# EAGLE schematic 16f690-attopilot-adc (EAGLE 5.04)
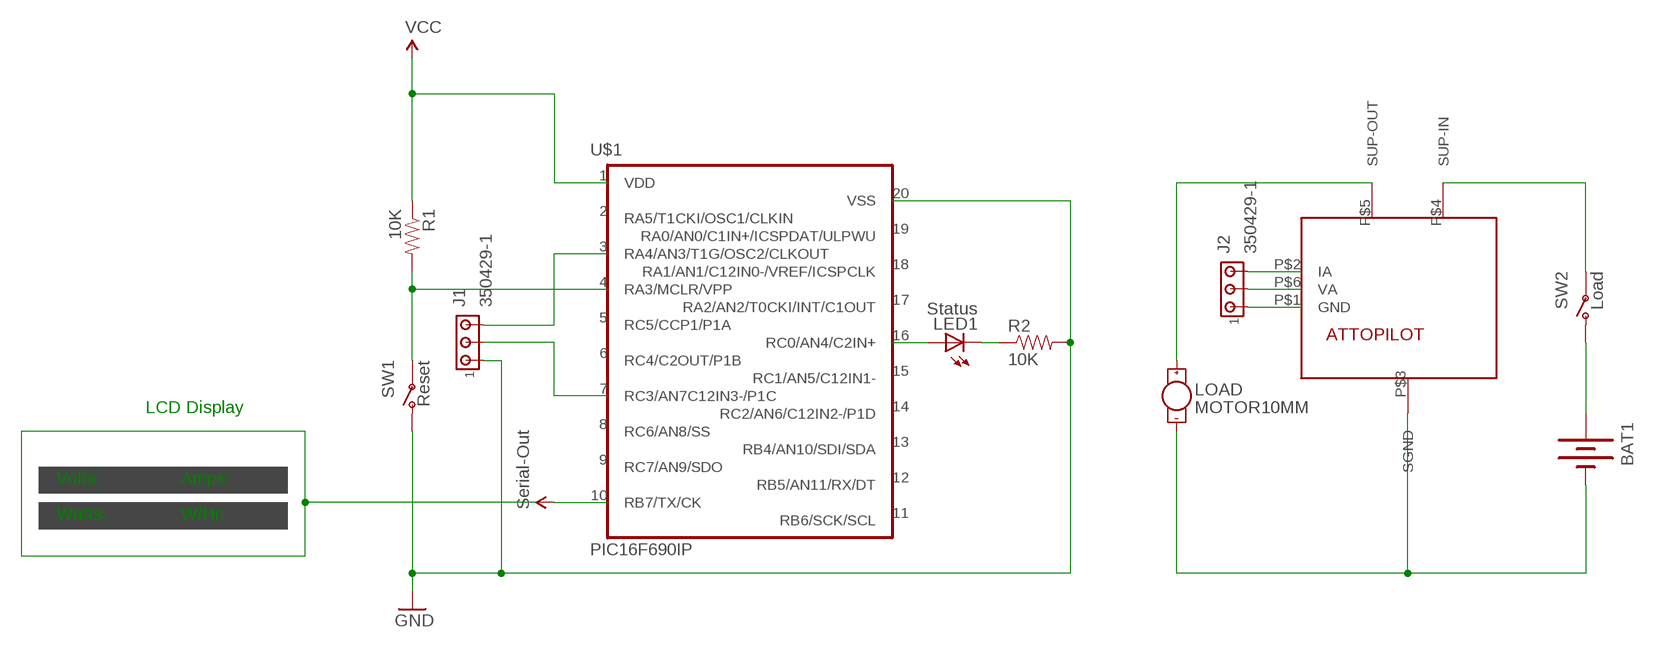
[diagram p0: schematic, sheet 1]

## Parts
ATTOPILOT  ATTOPILOT  [ATTOPILOT]
BAT1  BATTERYAA  [BATTERY-AA]
J1  350429-1  [350429-1]
J2  350429-1  [350429-1]
LED1  Status  LG_T679-E1F1-1  [PLCC2]
LOAD  MOTOR10MM  [VIBE-MOTOR-10MM]
R1  10K  RESISTORPTH1  [AXIAL-0.3]
R2  10K  RESISTORPTH1  [AXIAL-0.3]
SW1  Reset  SWITCH-SPST-2TV  [SWITCH-SPST-VERTICAL]
SW2  Load  SWITCH-SPST-2TV  [SWITCH-SPST-VERTICAL]
U$1  PIC16F690IP  [DIL20]

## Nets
GND: J1.1 R2.P$2 SW1.1(O) U$1.20(VSS)
N$1: ATTOPILOT.P$1(GND) J2.1
N$2: LED1.A U$1.16(RC0/AN4/C2IN+)
N$3: LED1.C R2.P$1
N$4: R1.P$2 SW1.2(P) U$1.4(RA3/MCLR/VPP)
N$5: ATTOPILOT.P$6(VA) J2.2
N$6: ATTOPILOT.P$2(IA) J2.3
N$7: BAT1.GND@1(-) LOAD.-
N$8: J1.3 U$1.3(RA4/AN3/T1G/OSC2/CLKOUT)
N$9: J1.2 U$1.7(RC3/AN7C12IN3-/P1C)
N$10: BAT1.PWR@1(+) SW2.1(O)
N$11: LOAD.+
N$12: SW2.2(P)
VCC: R1.P$1 U$1.1(VDD) U$1.10(RB7/TX/CK) ; supply symbol labelled Serial-Out
Unconnected: ATTOPILOT.P$3(SGND) ATTOPILOT.P$4(SUP-IN) ATTOPILOT.P$5(SUP-OUT) U$1.2(RA5/T1CKI/OSC1/CLKIN) U$1.5(RC5/CCP1/P1A) U$1.6(RC4/C2OUT/P1B) U$1.8(RC6/AN8/SS) U$1.9(RC7/AN9/SDO) U$1.11(RB6/SCK/SCL) U$1.12(RB5/AN11/RX/DT) U$1.13(RB4/AN10/SDI/SDA) U$1.14(RC2/AN6/C12IN2-/P1D) U$1.15(RC1/AN5/C12IN1-) U$1.17(RA2/AN2/T0CKI/INT/C1OUT) U$1.18(RA1/AN1/C12IN0-/VREF/ICSPCLK) U$1.19(RA0/AN0/C1IN+/ICSPDAT/ULPWU)

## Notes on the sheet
- LCD Display
- Volts: | Amps:
- Watts: | W/Hr:

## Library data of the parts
ATTOPILOT = trl:ATTOPILOT
BAT1 = SparkFun:BATTERY: Battery Holders
J1 J2 = con-amp:350429-1: Universal MATE-N-LOK .250" Centerline, 600 V, 19 - 36 A max Source: http://catalog.tycoelectronics.com/ .. ENG_CD_350429_Y.pdf
LED1 = led:*_T679-?-1: LC TOPLED® Low Current LED; COLOR: green
LOAD = SparkFun:MOTOR: Vibration Motor
R1 R2 = SparkFun:RESISTOR: Resistor
SW1 SW2 = SparkFun:SWITCH-SPST-2
U$1 = trl:PIC16F690*: MICROCONTROLLER PIC16F690 18 I/O One 16-bit timer Two 8-bit timer Two comparators Precision internal oscillator-software selectable 8 MHz - 32 KHz SSP w/ I2C Compatible Address mask option EUSART LIN 2.0 Compatible ECCP+ w/ PWM Steering 12 A/D Channels ULPW Enhanced Low Power Timer 1 Timer 1 Gate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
